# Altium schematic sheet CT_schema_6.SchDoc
size 430 x 414 mm
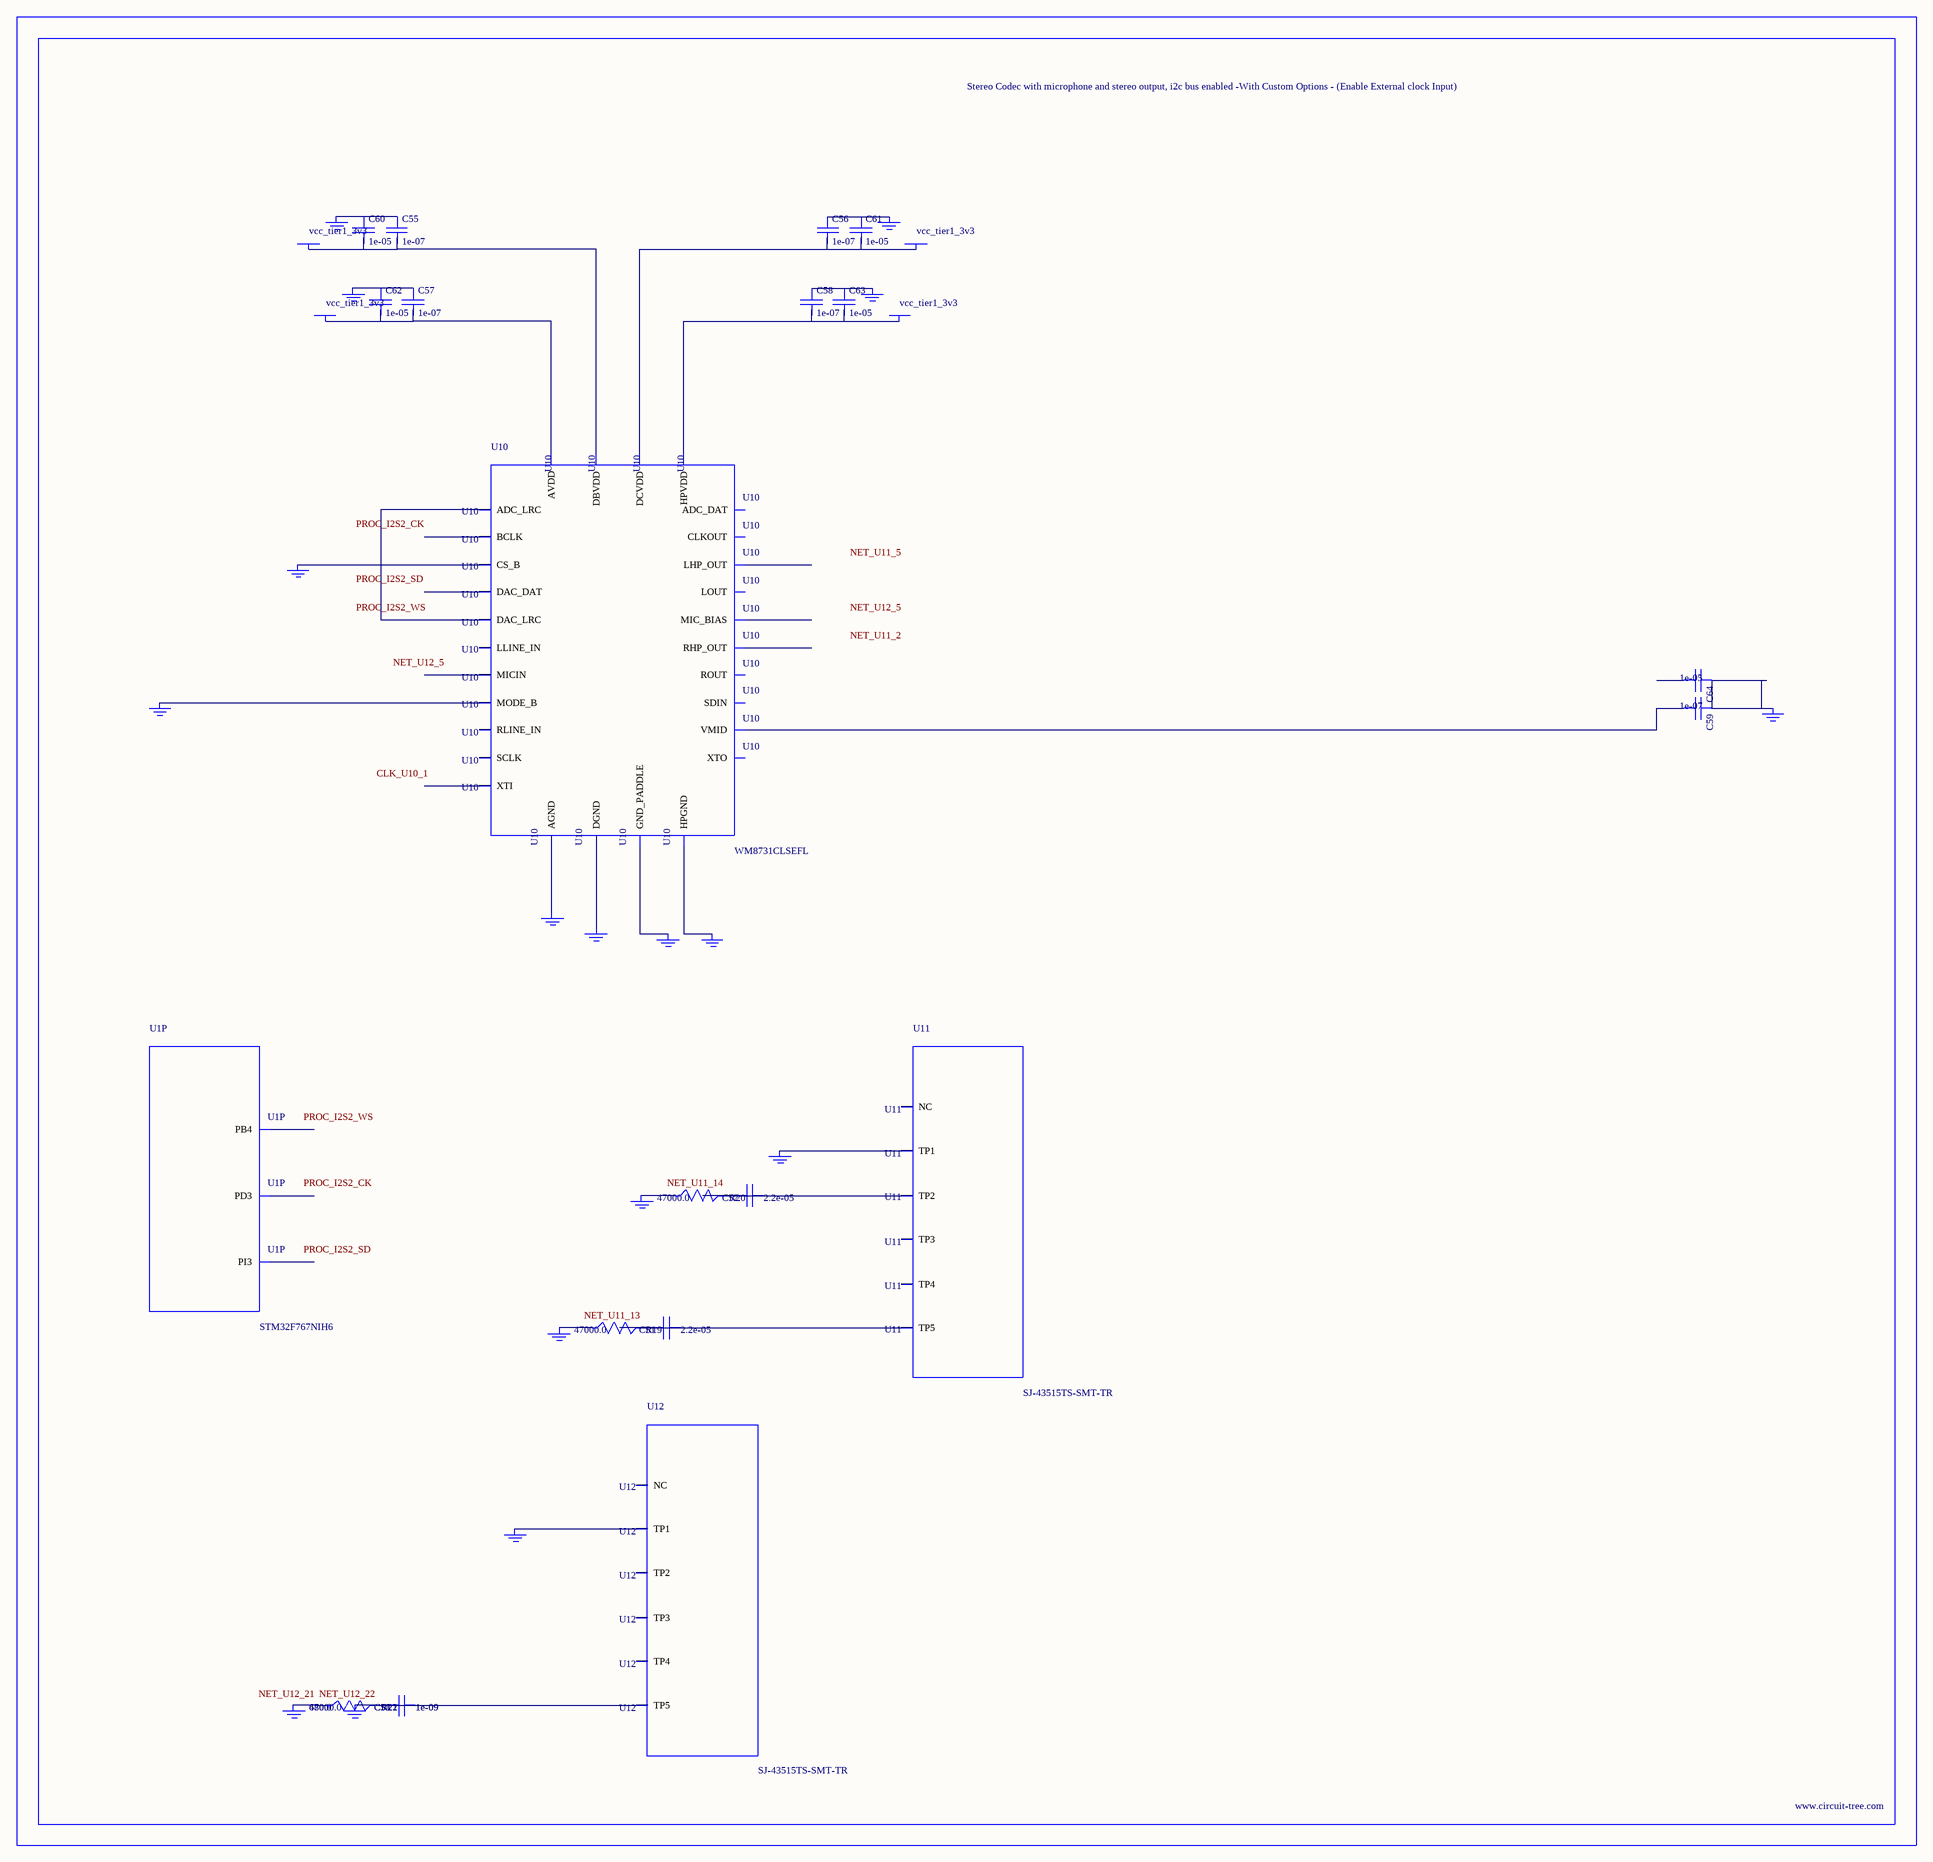
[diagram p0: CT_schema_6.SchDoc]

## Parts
BORDER5  (no value)
C51  2.2e-05  [C1210]
C52  2.2e-05  [C1210]
C53  1e-09  [C0402]
C54  1e-09  [C0402]
C55  1e-07  [C0402]
C56  1e-07  [C0402]
C57  1e-07  [C0402]
C58  1e-07  [C0402]
C59  1e-07  [C0402]
C60  1e-05  [C0805]
C61  1e-05  [C0805]
C62  1e-05  [C0805]
C63  1e-05  [C0805]
C64  1e-05  [C0805]
GND_INSTANCE_5_0  (no value)
GND_INSTANCE_5_1  (no value)
GND_INSTANCE_5_2  (no value)
GND_INSTANCE_5_3  (no value)
GND_INSTANCE_5_4  (no value)
GND_INSTANCE_5_5  (no value)
GND_INSTANCE_5_6  (no value)
GND_INSTANCE_5_7  (no value)
GND_INSTANCE_5_8  (no value)
GND_INSTANCE_5_9  (no value)
GND_INSTANCE_5_10  (no value)
GND_INSTANCE_5_11  (no value)
GND_INSTANCE_5_12  (no value)
GND_INSTANCE_5_13  (no value)
GND_INSTANCE_5_14  (no value)
GND_INSTANCE_5_15  (no value)
GND_INSTANCE_5_16  (no value)
POWER_INSTANCE_5_0  vcc_tier1_3v3
POWER_INSTANCE_5_1  vcc_tier1_3v3
POWER_INSTANCE_5_2  vcc_tier1_3v3
POWER_INSTANCE_5_3  vcc_tier1_3v3
R19  47000.0  [R0603]
R20  47000.0  [R0603]
R21  47000.0  [R0603]
R22  680.0  [R0603]
U1  STM32F767NIH6  [TFBGA216]  (part P of 16)
U10  WM8731CLSEFL  [QFN-28]
U11  SJ-43515TS-SMT-TR  [SJ-43515TS-SMT-TR]
U12  SJ-43515TS-SMT-TR  [SJ-43515TS-SMT-TR]

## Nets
NetC51_1: C51.1 C51.2 R19.2 U11.5(TP5)
NetC52_1: C52.1 C52.2 R20.2 U11.2(TP2)
NetC53_1: C53.1 C53.2 C54.1 C54.2 GND_INSTANCE_5_16.0(GND) R21.2 R22.2 U12.5(TP5)
NetC55_1: C55.1 C60.1 GND_INSTANCE_5_1.0(GND)
NetC55_2: C55.2 C60.2 POWER_INSTANCE_5_1.0(PWR) U10.5(DBVDD)
NetC56_1: C56.1 C61.1 GND_INSTANCE_5_0.0(GND)
NetC56_2: C56.2 C61.2 POWER_INSTANCE_5_0.0(PWR) U10.3(DCVDD)
NetC57_1: C57.1 C62.1 GND_INSTANCE_5_4.0(GND)
NetC57_2: C57.2 C62.2 POWER_INSTANCE_5_3.0(PWR) U10.18(AVDD)
NetC58_1: C58.1 C63.1 GND_INSTANCE_5_2.0(GND)
NetC58_2: C58.2 C63.2 POWER_INSTANCE_5_2.0(PWR) U10.12(HPVDD)
NetC59_1: C59.1 C64.1 GND_INSTANCE_5_5.0(GND)
NetC59_2: C59.2 U10.20(VMID)
NetGND_INSTANCE_5_3_0: GND_INSTANCE_5_3.0(GND) U10.15(HPGND)
NetGND_INSTANCE_5_6_0: GND_INSTANCE_5_6.0(GND) U10.25(MODE_B)
NetGND_INSTANCE_5_7_0: GND_INSTANCE_5_7.0(GND) U10.26(CS_B)
NetGND_INSTANCE_5_8_0: GND_INSTANCE_5_8.0(GND) U10.29(GND_PADDLE)
NetGND_INSTANCE_5_9_0: GND_INSTANCE_5_9.0(GND) U10.4(DGND)
NetGND_INSTANCE_5_10_0: GND_INSTANCE_5_10.0(GND) U10.19(AGND)
NetGND_INSTANCE_5_11_0: GND_INSTANCE_5_11.0(GND) U11.1(TP1)
NetGND_INSTANCE_5_12_0: GND_INSTANCE_5_12.0(GND) R20.1
NetGND_INSTANCE_5_13_0: GND_INSTANCE_5_13.0(GND) R19.1
NetGND_INSTANCE_5_14_0: GND_INSTANCE_5_14.0(GND) U12.1(TP1)
NetGND_INSTANCE_5_15_0: GND_INSTANCE_5_15.0(GND) R21.1 R22.1
NetU10_9: U10.9(DAC_LRC) U10.11(ADC_LRC)

Not connected (* = marked no-connect by the designer): C64 2; U1 A9(PB4) C11(PD3) C13(PI3); U10 1(XTI) 2(XTO) 6(CLKOUT) 7(BCLK) 8(DAC_DAT) 10(ADC_DAT) 13(LHP_OUT) 14(RHP_OUT) 16(LOUT) 17(ROUT) 21(MIC_BIAS) 22(MICIN) 23(RLINE_IN) 24(LLINE_IN) 27(SDIN) 28(SCLK); U11 3(TP3) 4(TP4) 6(NC); U12 2(TP2) 3(TP3) 4(TP4) 6(NC)

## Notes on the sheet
- Labels drawn without touching a wire or pin: CLK_U10_1, NET_U11_2, NET_U11_5, NET_U11_13, NET_U11_14, NET_U12_5, NET_U12_21, NET_U12_22, PROC_I2S2_CK, PROC_I2S2_SD, PROC_I2S2_WS

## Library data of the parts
BORDER5 = BORDER_PAGE5
C51 C52 = C1210C224K5RACTU
C53 C54 = C0402C102K3RAC
C55-C59 = C0402C104K3RACTU
C60-C64 = C0805C106K8RACTU
GND_INSTANCE_5_0-GND_INSTANCE_5_16 = GND
POWER_INSTANCE_5_0-POWER_INSTANCE_5_3 = PWR
R19-R21 = RC0603JR-0747KL
R22 = RC0603JR-07680RL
